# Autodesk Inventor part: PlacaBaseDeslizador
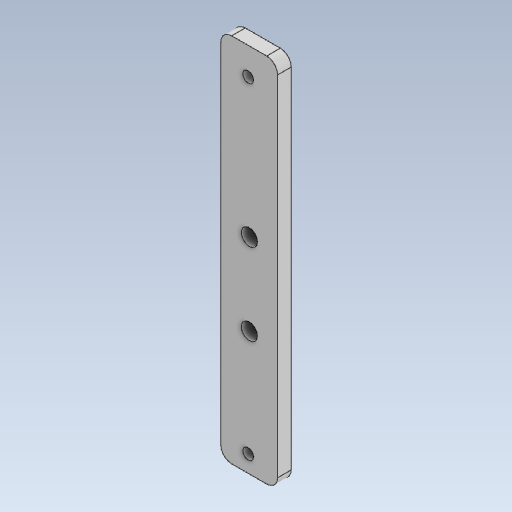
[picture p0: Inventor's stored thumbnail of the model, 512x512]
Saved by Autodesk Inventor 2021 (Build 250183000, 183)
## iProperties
Created: 2021-02
Part Number: PlacaBaseDeslizador
Material: Genérico
Document SubType Name: Modeling
Designer: ATOUZA
Density: 1 g/cm^3
Appearance: Valor por defecto
Author: ATOUZA
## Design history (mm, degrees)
node "Plano de trabajo1"
extrude "Extrusión1" new body sketch "Boceto1" distance "d8" = 5; taper "d9" = 0 deg
fillet "Empalme1" dims "d10" = 4
node "Sólido1"
other parameters: "d0" = 6, "d1" = 6, "d3" = 22.45, "d4" = 4, "d7" = 4
